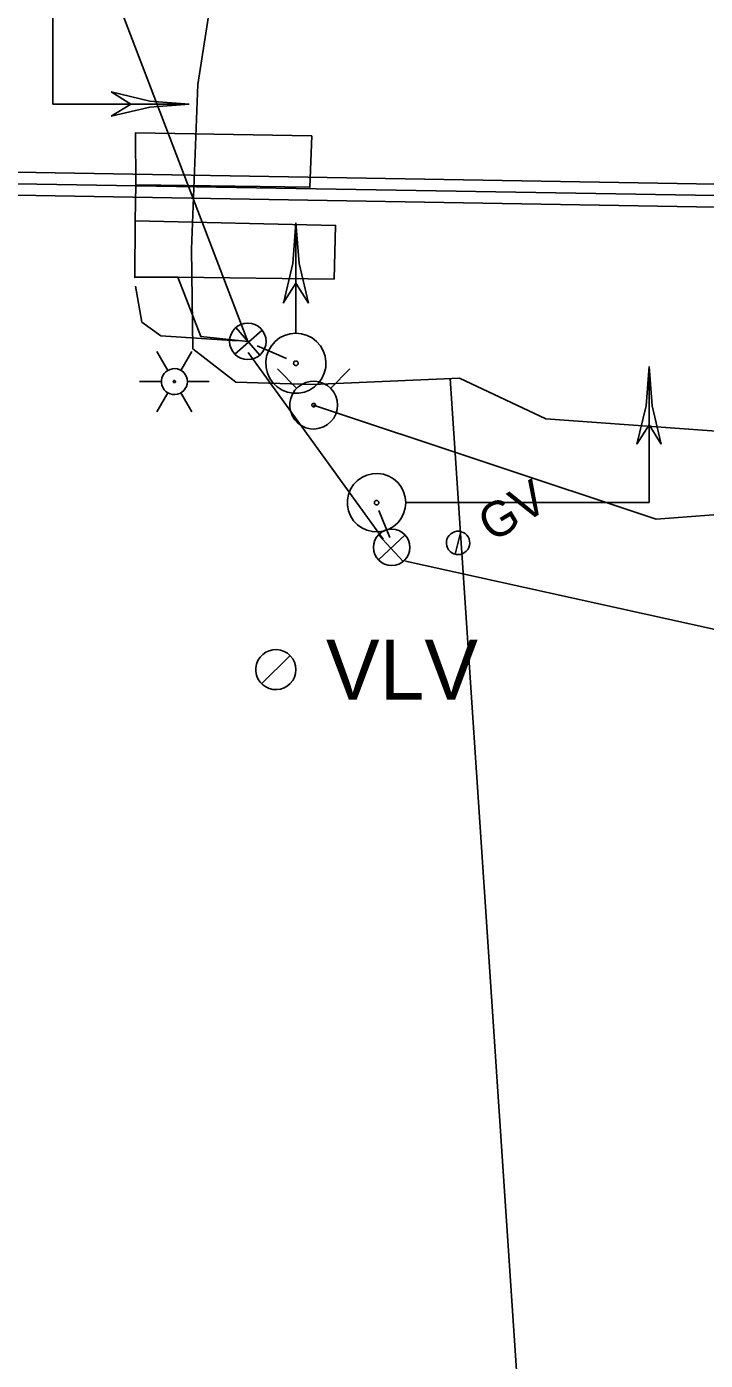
# Model space of a CAD drawing. Extents: x 596028 to 606371, y 330010 to 403088.
# Drawn here: x 604964 to 605038.5, y 337868.5 to 338014.8 of the extents above; entities that cross this region are included whole.
import ezdxf

# ---------------------------------------------------------------- set-up
doc = ezdxf.new("R2010")
doc.units = 0
for name, color, linetype in [('E_LTG', 7, 'Continuous'), ('E_SIG', 7, 'Continuous'), ('E_SIG_Conduit', 7, 'Continuous'), ('E_UTL_G', 7, 'Continuous'), ('E_UTL_G_UG', 7, 'Continuous'), ('E_UTL_Loop_UG', 7, 'Continuous'), ('E_UTL_SAN_UG_MMSD', 7, 'Continuous'), ('E_UTL_SAN_UG_OUTER_LIMITS', 7, 'Continuous'), ('E_UTL_VLV', 7, 'Continuous'), ('E_UTL_W_UG', 7, 'Continuous'), ('E_UTL_WHydrant', 7, 'Continuous')]:
    doc.layers.add(name, color=color, linetype=linetype)

# ---------------------------------------------------------------- blocks, each defined once
blk = doc.blocks.new('_U319')
at = {"layer": 'E_SIG'}
for p, q in [((0, 6.1), (0, -6.1)), ((-6.09, 0.4), (6.1, 0.4))]:
    blk.add_line(p, q, dxfattribs=at)
blk.add_circle((0, 0.01), 6.1, dxfattribs=at)
blk = doc.blocks.new('_U320')
at = {"layer": 'E_SIG'}
for p, q in [((0, 6.1), (0, -6.1)), ((-6.09, 0.4), (6.1, 0.4))]:
    blk.add_line(p, q, dxfattribs=at)
blk.add_circle((0, 0.01), 6.1, dxfattribs=at)

msp = doc.modelspace()

# ---------------------------------------------------------------- linework, layer by layer
at = {"layer": 'E_LTG'}
for points in [[(604979.53, 337977.11), (604978.33, 337979.17)], [(604980.95, 337977.11), (604982.15, 337979.17)], [(604981.67, 337975.87), (604981.64, 337976.14), (604981.57, 337976.41), (604981.44, 337976.65), (604981.27, 337976.86), (604981.07, 337977.04), (604980.83, 337977.17), (604980.58, 337977.26), (604980.31, 337977.3), (604980.04, 337977.29), (604979.77, 337977.22), (604979.53, 337977.11), (604979.3, 337976.95), (604979.12, 337976.76), (604978.97, 337976.53), (604978.87, 337976.28), (604978.82, 337976.01), (604978.82, 337975.74), (604978.87, 337975.47), (604978.97, 337975.22), (604979.12, 337974.99), (604979.3, 337974.79), (604979.53, 337974.64), (604979.77, 337974.52), (604980.04, 337974.46), (604980.31, 337974.45), (604980.58, 337974.49), (604980.83, 337974.57), (604981.07, 337974.71), (604981.27, 337974.89), (604981.44, 337975.1), (604981.57, 337975.34), (604981.64, 337975.6), (604981.67, 337975.87)], [(604981.67, 337975.87), (604981.64, 337976.14), (604981.57, 337976.41), (604981.44, 337976.65), (604981.27, 337976.86), (604981.07, 337977.04), (604980.83, 337977.17), (604980.58, 337977.26), (604980.31, 337977.3), (604980.04, 337977.29), (604979.77, 337977.22), (604979.53, 337977.11), (604979.3, 337976.95), (604979.12, 337976.76), (604978.97, 337976.53), (604978.87, 337976.28), (604978.82, 337976.01), (604978.82, 337975.74), (604978.87, 337975.47), (604978.97, 337975.22), (604979.12, 337974.99), (604979.3, 337974.79), (604979.53, 337974.64), (604979.77, 337974.52), (604980.04, 337974.46), (604980.31, 337974.45), (604980.58, 337974.49), (604980.83, 337974.57), (604981.07, 337974.71), (604981.27, 337974.89), (604981.44, 337975.1), (604981.57, 337975.34), (604981.64, 337975.6), (604981.67, 337975.87)], [(604981.67, 337975.87), (604981.64, 337976.14), (604981.57, 337976.41), (604981.44, 337976.65), (604981.27, 337976.86), (604981.07, 337977.04), (604980.83, 337977.17), (604980.58, 337977.26), (604980.31, 337977.3), (604980.04, 337977.29), (604979.77, 337977.22), (604979.53, 337977.11), (604979.3, 337976.95), (604979.12, 337976.76), (604978.97, 337976.53), (604978.87, 337976.28), (604978.82, 337976.01), (604978.82, 337975.74), (604978.87, 337975.47), (604978.97, 337975.22), (604979.12, 337974.99), (604979.3, 337974.79), (604979.53, 337974.64), (604979.77, 337974.52), (604980.04, 337974.46), (604980.31, 337974.45), (604980.58, 337974.49), (604980.83, 337974.57), (604981.07, 337974.71), (604981.27, 337974.89), (604981.44, 337975.1), (604981.57, 337975.34), (604981.64, 337975.6), (604981.67, 337975.87)], [(604976.43, 337975.87), (604978.81, 337975.87)], [(604980.36, 337975.87), (604980.36, 337975.9), (604980.35, 337975.92), (604980.34, 337975.94), (604980.33, 337975.96), (604980.31, 337975.97), (604980.29, 337975.98), (604980.27, 337975.99), (604980.25, 337975.99), (604980.22, 337975.99), (604980.2, 337975.99), (604980.18, 337975.98), (604980.16, 337975.96), (604980.15, 337975.95), (604980.13, 337975.93), (604980.13, 337975.91), (604980.12, 337975.89), (604980.12, 337975.86), (604980.13, 337975.84), (604980.13, 337975.82), (604980.15, 337975.8), (604980.16, 337975.78), (604980.18, 337975.77), (604980.2, 337975.76), (604980.22, 337975.76), (604980.25, 337975.76), (604980.27, 337975.76), (604980.29, 337975.77), (604980.31, 337975.78), (604980.33, 337975.79), (604980.34, 337975.81), (604980.35, 337975.83), (604980.36, 337975.85), (604980.36, 337975.87)], [(604981.67, 337975.87), (604984.05, 337975.87)], [(604978.33, 337972.57), (604979.53, 337974.64)], [(604982.15, 337972.57), (604980.95, 337974.64)]]:
    msp.add_lwpolyline(points, dxfattribs=at)
at = {"layer": 'E_SIG'}
for points in [[(604966.91, 338006.33), (604966.91, 338032.97)], [(604966.91, 338013.8), (604966.91, 338013.8)], [(604975.45, 338006.33), (604973.32, 338007.67)], [(604981.86, 338006.33), (604977.54, 338006.66), (604973.32, 338007.66)], [(604966.91, 338006.33), (604981.86, 338006.33)], [(604981.86, 338006.33), (604977.54, 338005.99), (604973.32, 338004.99)], [(604973.32, 338004.99), (604975.45, 338006.33)], [(604993.57, 337993.28), (604993.22, 337988.83), (604992.2, 337984.48)], [(604993.57, 337993.28), (604993.57, 337981.24)], [(604993.57, 337993.28), (604993.92, 337988.83), (604994.95, 337984.48)], [(604993.57, 337986.69), (604992.19, 337984.49)], [(604994.94, 337984.49), (604993.57, 337986.69)], [(604993.57, 337981.18), (604992.95, 337981.13), (604992.34, 337980.95), (604991.79, 337980.66), (604991.29, 337980.27), (604990.88, 337979.8), (604990.57, 337979.26), (604990.36, 337978.66), (604990.27, 337978.04), (604990.3, 337977.42), (604990.45, 337976.81), (604990.71, 337976.23), (604991.08, 337975.72), (604991.53, 337975.29), (604992.06, 337974.95), (604992.64, 337974.72), (604993.26, 337974.6), (604993.88, 337974.6), (604994.5, 337974.72), (604995.08, 337974.95), (604995.61, 337975.29), (604996.06, 337975.72), (604996.43, 337976.23), (604996.69, 337976.81), (604996.84, 337977.42), (604996.87, 337978.04), (604996.78, 337978.66), (604996.57, 337979.26), (604996.26, 337979.8), (604995.85, 337980.27), (604995.35, 337980.66), (604994.8, 337980.95), (604994.2, 337981.13), (604993.57, 337981.18)], [(604993.57, 337978.14), (604993.52, 337978.13), (604993.48, 337978.12), (604993.43, 337978.1), (604993.4, 337978.07), (604993.36, 337978.03), (604993.34, 337977.99), (604993.33, 337977.94), (604993.32, 337977.9), (604993.32, 337977.85), (604993.33, 337977.8), (604993.35, 337977.76), (604993.38, 337977.72), (604993.41, 337977.69), (604993.45, 337977.66), (604993.5, 337977.64), (604993.55, 337977.63), (604993.59, 337977.63), (604993.64, 337977.64), (604993.69, 337977.66), (604993.73, 337977.69), (604993.76, 337977.72), (604993.79, 337977.76), (604993.81, 337977.8), (604993.82, 337977.85), (604993.82, 337977.9), (604993.82, 337977.94), (604993.8, 337977.99), (604993.78, 337978.03), (604993.74, 337978.07), (604993.71, 337978.1), (604993.66, 337978.12), (604993.62, 337978.13), (604993.57, 337978.14)], [(605032.31, 337977.54), (605031.98, 337973.22), (605030.98, 337969)], [(605032.31, 337962.6), (605032.31, 337977.54)], [(605032.31, 337977.54), (605032.65, 337973.22), (605033.65, 337969)], [(605032.31, 337971.14), (605030.98, 337969)], [(605033.65, 337969), (605032.31, 337971.14)], [(605005.62, 337962.59), (605005.57, 337963.2), (605005.39, 337963.78), (605005.12, 337964.33), (605004.74, 337964.8), (605004.28, 337965.2), (605003.75, 337965.51), (605003.18, 337965.71), (605002.57, 337965.79), (605001.96, 337965.76), (605001.37, 337965.62), (605000.82, 337965.37), (605000.32, 337965.02), (604999.9, 337964.57), (604999.57, 337964.06), (604999.35, 337963.5), (604999.23, 337962.9), (604999.23, 337962.29), (604999.35, 337961.69), (604999.57, 337961.13), (604999.9, 337960.61), (605000.32, 337960.17), (605000.82, 337959.82), (605001.37, 337959.57), (605001.96, 337959.42), (605002.57, 337959.4), (605003.18, 337959.48), (605003.75, 337959.68), (605004.28, 337959.99), (605004.74, 337960.38), (605005.12, 337960.86), (605005.39, 337961.4), (605005.57, 337961.99), (605005.62, 337962.59)], [(605002.67, 337962.59), (605002.66, 337962.64), (605002.65, 337962.69), (605002.63, 337962.73), (605002.6, 337962.76), (605002.56, 337962.79), (605002.52, 337962.82), (605002.48, 337962.83), (605002.43, 337962.84), (605002.39, 337962.84), (605002.34, 337962.83), (605002.3, 337962.81), (605002.26, 337962.78), (605002.23, 337962.75), (605002.2, 337962.71), (605002.19, 337962.66), (605002.18, 337962.62), (605002.18, 337962.57), (605002.19, 337962.53), (605002.2, 337962.48), (605002.23, 337962.44), (605002.26, 337962.41), (605002.3, 337962.38), (605002.34, 337962.36), (605002.39, 337962.35), (605002.43, 337962.35), (605002.48, 337962.36), (605002.52, 337962.37), (605002.56, 337962.39), (605002.6, 337962.43), (605002.63, 337962.46), (605002.65, 337962.5), (605002.66, 337962.55), (605002.67, 337962.59)], [(605032.31, 337962.6), (605005.68, 337962.6)], [(605024.84, 337962.6), (605024.84, 337962.6)]]:
    msp.add_lwpolyline(points, dxfattribs=at)
at = {"layer": 'E_SIG_Conduit'}
for points in [[(604988.3, 337980.29), (604966.91, 338036.22)], [(604988.3, 337980.29), (604983.13, 337980.83), (604980.62, 337987.34)], [(604989.34, 337979.81), (604992.54, 337978.41)], [(605003.14, 337958.57), (604988.32, 337979.06)], [(605003.88, 337958.76), (605002.66, 337961.74)], [(605005.59, 337956.19), (605047.35, 337946.97)]]:
    msp.add_lwpolyline(points, dxfattribs=at)
at = {"layer": 'E_UTL_G'}
for points in [[(605012.46, 337958.84), (605012.31, 337959.03), (605012.14, 337959.2), (605011.93, 337959.33), (605011.7, 337959.41), (605011.46, 337959.45), (605011.22, 337959.45), (605010.98, 337959.4), (605010.75, 337959.3), (605010.55, 337959.17), (605010.38, 337959), (605010.24, 337958.8), (605010.14, 337958.57), (605010.09, 337958.33), (605010.08, 337958.09), (605010.12, 337957.85), (605010.2, 337957.62), (605010.33, 337957.41), (605010.49, 337957.23), (605010.69, 337957.08), (605010.9, 337956.97), (605011.14, 337956.91), (605011.38, 337956.89), (605011.63, 337956.92), (605011.86, 337956.99), (605012.07, 337957.11), (605012.26, 337957.26), (605012.42, 337957.45), (605012.54, 337957.66), (605012.61, 337957.89), (605012.64, 337958.14), (605012.63, 337958.38), (605012.57, 337958.62), (605012.46, 337958.84)], [(605011.05, 337956.93), (605011.67, 337959.42)]]:
    msp.add_lwpolyline(points, dxfattribs=at)
at = {"layer": 'E_UTL_G_UG'}
msp.add_line((605023.49, 337782.11), (605010.48, 337976.21), dxfattribs=at)
msp.add_lwpolyline([(604985.13, 338025.8), (604984.31, 338018.12), (604982.82, 338008.48), (604982.14, 337990.42), (604982.27, 337979.47), (604987, 337975.81), (604995.42, 337975.54), (605011.51, 337976.25), (605020.99, 337971.8), (605053.36, 337969.44), (605062.73, 337971.35), (605086.18, 337973.75), (605099.06, 337974.9), (605119.67, 337972.71), (605158.32, 337969.58), (605188.11, 337968.3), (605207.41, 337968.58), (605224.32, 337967.71), (605236.94, 337968.08), (605244.48, 337969.02), (605249.45, 337969.46), (605249.24, 337972.16), (605249.24, 337972.53)], dxfattribs=at)
at = {"layer": 'E_UTL_Loop_UG'}
for points in [[(604976.01, 337997.48), (604995.12, 337997.19), (604995.32, 338002.84), (604975.98, 338003.17), (604976.01, 337997.48)], [(604975.95, 337993.55), (604976.01, 337997.48)], [(604980.62, 337987.34), (604980.62, 337987.34), (604997.76, 337987.12), (604997.93, 337993.01), (604975.95, 337993.5), (604975.9, 337987.28), (604975.95, 337993.55)], [(604980.62, 337987.34), (604975.9, 337987.34)], [(604987.14, 337980.36), (604978.74, 337980.91), (604976.69, 337982.4), (604975.97, 337986.35)]]:
    msp.add_lwpolyline(points, dxfattribs=at)
at = {"layer": 'E_UTL_SAN_UG_MMSD'}
msp.add_line((604679.67, 338002.43), (605085.21, 337995.5), dxfattribs=at)
at = {"layer": 'E_UTL_SAN_UG_OUTER_LIMITS'}
for p, q in [((604679.59, 338003.68), (605084.89, 337996.75)), ((604679.53, 338001.18), (605085.18, 337994.25))]:
    msp.add_line(p, q, dxfattribs=at)
at = {"layer": 'E_UTL_VLV'}
for points in [[(604993.57, 337944.27), (604993.53, 337944.69), (604993.41, 337945.09), (604993.22, 337945.46), (604992.96, 337945.79), (604992.65, 337946.07), (604992.28, 337946.28), (604991.89, 337946.41), (604991.47, 337946.47), (604991.06, 337946.45), (604990.65, 337946.35), (604990.27, 337946.18), (604989.93, 337945.94), (604989.64, 337945.63), (604989.41, 337945.28), (604989.26, 337944.89), (604989.18, 337944.48), (604989.18, 337944.06), (604989.26, 337943.65), (604989.41, 337943.27), (604989.64, 337942.91), (604989.93, 337942.61), (604990.27, 337942.37), (604990.65, 337942.2), (604991.06, 337942.1), (604991.47, 337942.08), (604991.89, 337942.14), (604992.28, 337942.27), (604992.65, 337942.48), (604992.96, 337942.76), (604993.22, 337943.08), (604993.41, 337943.46), (604993.53, 337943.86), (604993.57, 337944.27)], [(604989.81, 337942.72), (604992.93, 337945.83)]]:
    msp.add_lwpolyline(points, dxfattribs=at)
at = {"layer": 'E_UTL_W_UG'}
msp.add_lwpolyline([(604995.52, 337973.29), (605033.1, 337960.78), (605040.83, 337961.35)], dxfattribs=at)
at = {"layer": 'E_UTL_WHydrant'}
for points in [[(604993.69, 337975.13), (604991.54, 337977.27)], [(604997.36, 337975.13), (604999.5, 337977.27)], [(604998.14, 337973.29), (604998.1, 337973.79), (604997.95, 337974.27), (604997.73, 337974.71), (604997.42, 337975.1), (604997.04, 337975.43), (604996.61, 337975.68), (604996.14, 337975.84), (604995.64, 337975.91), (604995.15, 337975.89), (604994.66, 337975.77), (604994.21, 337975.57), (604993.8, 337975.28), (604993.46, 337974.92), (604993.19, 337974.5), (604993, 337974.03), (604992.91, 337973.54), (604992.91, 337973.04), (604993, 337972.56), (604993.19, 337972.09), (604993.46, 337971.67), (604993.8, 337971.31), (604994.21, 337971.02), (604994.66, 337970.82), (604995.15, 337970.7), (604995.64, 337970.67), (604996.14, 337970.75), (604996.61, 337970.91), (604997.04, 337971.16), (604997.42, 337971.48), (604997.73, 337971.88), (604997.95, 337972.32), (604998.1, 337972.8), (604998.14, 337973.29)], [(604995.72, 337973.29), (604995.72, 337973.33), (604995.71, 337973.37), (604995.69, 337973.4), (604995.67, 337973.43), (604995.64, 337973.46), (604995.6, 337973.48), (604995.57, 337973.49), (604995.53, 337973.49), (604995.49, 337973.49), (604995.45, 337973.48), (604995.42, 337973.47), (604995.39, 337973.45), (604995.36, 337973.42), (604995.34, 337973.39), (604995.33, 337973.35), (604995.32, 337973.31), (604995.32, 337973.28), (604995.33, 337973.24), (604995.34, 337973.2), (604995.36, 337973.17), (604995.39, 337973.14), (604995.42, 337973.12), (604995.45, 337973.1), (604995.49, 337973.1), (604995.53, 337973.09), (604995.57, 337973.1), (604995.6, 337973.11), (604995.64, 337973.13), (604995.67, 337973.16), (604995.69, 337973.19), (604995.71, 337973.22), (604995.72, 337973.26), (604995.72, 337973.29)]]:
    msp.add_lwpolyline(points, dxfattribs=at)

# ---------------------------------------------------------------- block references
at = {"layer": 'E_SIG_Conduit', "xscale": 0.32808333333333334, "yscale": 0.32808333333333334}
for name, p, rotation in [('_U320', (604988.3, 337980.29), -138.82104477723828), ('_U319', (605004.09, 337957.69), 132.75965935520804)]:
    msp.add_blockref(name, p, dxfattribs=dict(at, rotation=rotation))

# ---------------------------------------------------------------- texts
at = {"layer": 'E_UTL_G'}
msp.add_text('GV', height=3.85, rotation=31.0271, dxfattribs=at).set_placement((605015.1, 337958.18))
at = {"layer": 'E_UTL_VLV'}
msp.add_text('VLV', height=6.6, dxfattribs=at).set_placement((604996.87, 337940.97))

doc.saveas('drawing.dxf')
